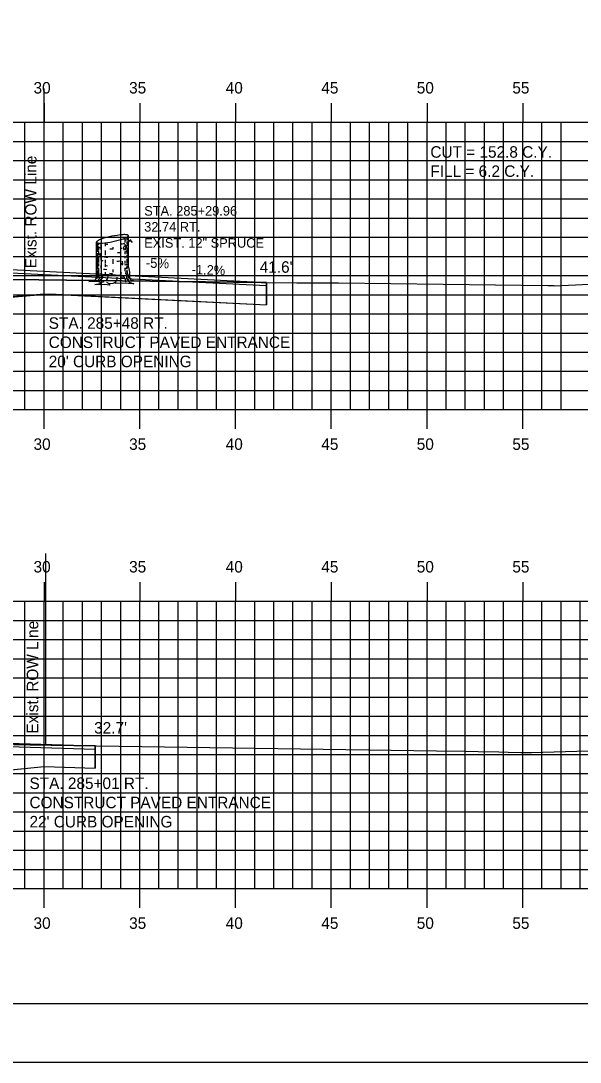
# Model space of a CAD drawing. Extents: x 856680 to 856850, y 366268 to 366378.
# Drawn here: x 856791.9 to 856821.1, y 366268.2 to 366322.5 of the extents above; entities that cross this region are included whole.
import ezdxf

# ---------------------------------------------------------------- set-up
doc = ezdxf.new("R2010")
doc.units = 0
for name, color, linetype in [('ANNOTATION', 7, 'Continuous'), ('BORDER', 7, 'Continuous'), ('D_Roadway_Drive_Gravel_RT', 7, 'Continuous'), ('D_Roadway_Drive_SubGrade', 7, 'Continuous'), ('D_Text_Monospaced', 7, 'Continuous'), ('D_Text_Standard', 7, 'Continuous'), ('E_ROW_Line', 7, 'Continuous'), ('H_V ANNOTATION', 7, 'Continuous'), ('JUNK COM EXC', 7, 'Continuous'), ('MAJOR', 7, 'Continuous'), ('MINOR', 7, 'Continuous'), ('PLOT BOUNDARY', 7, 'Continuous'), ('S_Roadway_Centerline', 7, 'Continuous'), ('S_Trees_Conifer_Pay', 7, 'Continuous')]:
    doc.layers.add(name, color=color, linetype=linetype)

msp = doc.modelspace()

# ---------------------------------------------------------------- linework, layer by layer
at = {"layer": 'BORDER'}
msp.add_line((856688.116, 366271.236), (856848.116, 366271.236), dxfattribs=at)
at = {"layer": 'D_Roadway_Drive_Gravel_RT'}
for p, q in [((856787.117, 366309.756), (856804.736, 366308.875)), ((856787.108, 366309.589), (856804.736, 366308.708)), ((856793.116, 366308.288), (856804.736, 366307.707)), ((856787.112, 366284.786), (856795.791, 366284.523)), ((856787.117, 366284.953), (856795.791, 366284.69)), ((856793.116, 366283.608), (856795.791, 366283.523))]:
    msp.add_line(p, q, dxfattribs=at)
at = {"layer": 'D_Roadway_Drive_SubGrade'}
for p, q in [((856804.736, 366308.875), (856804.736, 366307.708)), ((856783.116, 366307.402), (856793.116, 366308.288)), ((856795.791, 366284.69), (856795.791, 366283.523)), ((856783.116, 366282.599), (856793.116, 366283.608))]:
    msp.add_line(p, q, dxfattribs=at)
at = {"layer": 'E_ROW_Line'}
for p, q in [((856793.119, 366309.007), (856793.119, 366319.007)), ((856793.211, 366284.728), (856793.211, 366294.728))]:
    msp.add_line(p, q, dxfattribs=at)
at = {"layer": 'JUNK COM EXC'}
msp.add_lwpolyline([(856783.116, 366309.234), (856783.116, 366307.402), (856783.116, 366307.402), (856793.404, 366308.273), (856804.736, 366307.707), (856804.736, 366308.874), (856804.736, 366308.874), (856804.446, 366308.878), (856788.463, 366309.06), (856786.682, 366309.152), (856785.792, 366309.195), (856784.53, 366309.232), (856783.77, 366309.239), (856783.307, 366309.238), (856783.116, 366309.234)], dxfattribs=at)
msp.add_lwpolyline([(856783.116, 366284.8), (856783.116, 366282.599), (856783.116, 366282.599), (856793.116, 366283.608), (856795.791, 366283.523), (856795.791, 366284.69), (856793.483, 366284.724), (856792.375, 366284.743), (856791.541, 366284.755), (856789.691, 366284.768), (856786.527, 366284.756), (856783.225, 366284.802)], close=True, dxfattribs=at)
at = {"layer": 'MAJOR'}
for p, q in [((856793.116, 366318.238), (856793.116, 366317.236)), ((856798.116, 366318.238), (856798.116, 366317.236)), ((856803.116, 366318.238), (856803.116, 366317.236)), ((856808.116, 366318.238), (856808.116, 366317.236)), ((856813.116, 366318.238), (856813.116, 366317.236)), ((856818.116, 366318.238), (856818.116, 366317.236)), ((856693.116, 366317.236), (856833.116, 366317.236)), ((856693.116, 366317.236), (856833.116, 366317.236)), ((856793.116, 366302.236), (856793.116, 366317.236)), ((856798.116, 366302.236), (856798.116, 366317.236)), ((856803.116, 366302.236), (856803.116, 366317.236)), ((856808.116, 366302.236), (856808.116, 366317.236)), ((856813.116, 366302.236), (856813.116, 366317.236)), ((856818.116, 366302.236), (856818.116, 366317.236)), ((856693.116, 366312.236), (856833.116, 366312.236)), ((856693.116, 366307.236), (856833.116, 366307.236)), ((856693.116, 366302.236), (856833.116, 366302.236)), ((856693.116, 366302.236), (856833.116, 366302.236)), ((856793.116, 366301.234), (856793.116, 366302.236)), ((856798.116, 366301.234), (856798.116, 366302.236)), ((856803.116, 366301.234), (856803.116, 366302.236)), ((856808.116, 366301.234), (856808.116, 366302.236)), ((856813.116, 366301.234), (856813.116, 366302.236)), ((856818.116, 366301.234), (856818.116, 366302.236)), ((856793.116, 366293.238), (856793.116, 366292.236)), ((856798.116, 366293.238), (856798.116, 366292.236)), ((856803.116, 366293.238), (856803.116, 366292.236)), ((856808.116, 366293.238), (856808.116, 366292.236)), ((856813.116, 366293.238), (856813.116, 366292.236)), ((856818.116, 366293.238), (856818.116, 366292.236)), ((856693.116, 366292.236), (856833.116, 366292.236)), ((856693.116, 366292.236), (856833.116, 366292.236)), ((856793.116, 366277.236), (856793.116, 366292.236)), ((856798.116, 366277.236), (856798.116, 366292.236)), ((856803.116, 366277.236), (856803.116, 366292.236)), ((856808.116, 366277.236), (856808.116, 366292.236)), ((856813.116, 366277.236), (856813.116, 366292.236)), ((856818.116, 366277.236), (856818.116, 366292.236)), ((856693.116, 366287.236), (856833.116, 366287.236)), ((856693.116, 366282.236), (856833.116, 366282.236)), ((856693.116, 366277.236), (856833.116, 366277.236)), ((856693.116, 366277.236), (856833.116, 366277.236)), ((856793.116, 366276.234), (856793.116, 366277.236)), ((856798.116, 366276.234), (856798.116, 366277.236)), ((856803.116, 366276.234), (856803.116, 366277.236)), ((856808.116, 366276.234), (856808.116, 366277.236)), ((856813.116, 366276.234), (856813.116, 366277.236)), ((856818.116, 366276.234), (856818.116, 366277.236))]:
    msp.add_line(p, q, dxfattribs=at)
at = {"layer": 'MINOR'}
for p, q in [((856792.116, 366302.236), (856792.116, 366317.236)), ((856794.116, 366302.236), (856794.116, 366317.236)), ((856795.116, 366302.236), (856795.116, 366317.236)), ((856796.116, 366302.236), (856796.116, 366317.236)), ((856797.116, 366302.236), (856797.116, 366317.236)), ((856799.116, 366302.236), (856799.116, 366317.236)), ((856800.116, 366302.236), (856800.116, 366317.236)), ((856801.116, 366302.236), (856801.116, 366317.236)), ((856802.116, 366302.236), (856802.116, 366317.236)), ((856804.116, 366302.236), (856804.116, 366317.236)), ((856805.116, 366302.236), (856805.116, 366317.236)), ((856806.116, 366302.236), (856806.116, 366317.236)), ((856807.116, 366302.236), (856807.116, 366317.236)), ((856809.116, 366302.236), (856809.116, 366317.236)), ((856810.116, 366302.236), (856810.116, 366317.236)), ((856811.116, 366302.236), (856811.116, 366317.236)), ((856812.116, 366302.236), (856812.116, 366317.236)), ((856814.116, 366302.236), (856814.116, 366317.236)), ((856815.116, 366302.236), (856815.116, 366317.236)), ((856816.116, 366302.236), (856816.116, 366317.236)), ((856817.116, 366302.236), (856817.116, 366317.236)), ((856819.116, 366302.236), (856819.116, 366317.236)), ((856820.116, 366302.236), (856820.116, 366317.236)), ((856693.116, 366316.236), (856833.116, 366316.236)), ((856693.116, 366315.236), (856833.116, 366315.236)), ((856693.116, 366314.236), (856833.116, 366314.236)), ((856693.116, 366313.236), (856833.116, 366313.236)), ((856693.116, 366311.236), (856833.116, 366311.236)), ((856693.116, 366310.236), (856833.116, 366310.236)), ((856693.116, 366309.236), (856833.116, 366309.236)), ((856693.116, 366308.236), (856833.116, 366308.236)), ((856693.116, 366306.236), (856833.116, 366306.236)), ((856693.116, 366305.236), (856833.116, 366305.236)), ((856693.116, 366304.236), (856833.116, 366304.236)), ((856693.116, 366303.236), (856833.116, 366303.236)), ((856792.116, 366277.236), (856792.116, 366292.236)), ((856794.116, 366277.236), (856794.116, 366292.236)), ((856795.116, 366277.236), (856795.116, 366292.236)), ((856796.116, 366277.236), (856796.116, 366292.236)), ((856797.116, 366277.236), (856797.116, 366292.236)), ((856799.116, 366277.236), (856799.116, 366292.236)), ((856800.116, 366277.236), (856800.116, 366292.236)), ((856801.116, 366277.236), (856801.116, 366292.236)), ((856802.116, 366277.236), (856802.116, 366292.236)), ((856804.116, 366277.236), (856804.116, 366292.236)), ((856805.116, 366277.236), (856805.116, 366292.236)), ((856806.116, 366277.236), (856806.116, 366292.236)), ((856807.116, 366277.236), (856807.116, 366292.236)), ((856809.116, 366277.236), (856809.116, 366292.236)), ((856810.116, 366277.236), (856810.116, 366292.236)), ((856811.116, 366277.236), (856811.116, 366292.236)), ((856812.116, 366277.236), (856812.116, 366292.236)), ((856814.116, 366277.236), (856814.116, 366292.236)), ((856815.116, 366277.236), (856815.116, 366292.236)), ((856816.116, 366277.236), (856816.116, 366292.236)), ((856817.116, 366277.236), (856817.116, 366292.236)), ((856819.116, 366277.236), (856819.116, 366292.236)), ((856820.116, 366277.236), (856820.116, 366292.236)), ((856821.116, 366277.236), (856821.116, 366292.236)), ((856693.116, 366291.236), (856833.116, 366291.236)), ((856693.116, 366290.236), (856833.116, 366290.236)), ((856693.116, 366289.236), (856833.116, 366289.236)), ((856693.116, 366288.236), (856833.116, 366288.236)), ((856693.116, 366286.236), (856833.116, 366286.236)), ((856693.116, 366285.236), (856833.116, 366285.236)), ((856693.116, 366284.236), (856833.116, 366284.236)), ((856693.116, 366283.236), (856833.116, 366283.236)), ((856693.116, 366281.236), (856833.116, 366281.236)), ((856693.116, 366280.236), (856833.116, 366280.236)), ((856693.116, 366279.236), (856833.116, 366279.236)), ((856693.116, 366278.236), (856833.116, 366278.236))]:
    msp.add_line(p, q, dxfattribs=at)
at = {"layer": 'PLOT BOUNDARY'}
msp.add_lwpolyline([(856680.023, 366268.177), (856850.023, 366268.177), (856850.023, 366378.177), (856680.023, 366378.177)], close=True, dxfattribs=at)
at = {"layer": 'S_Roadway_Centerline'}
for points in [[(856788.463, 366309.06), (856804.446, 366308.878), (856806.319, 366308.852), (856807.253, 366308.849), (856807.696, 366308.849), (856808.101, 366308.85), (856808.281, 366308.851), (856808.489, 366308.853), (856819.433, 366308.709), (856819.506, 366308.709), (856819.606, 366308.709), (856819.725, 366308.708), (856819.769, 366308.707), (856821.607, 366308.779), (856833.116, 366308.838)], [(856791.541, 366284.755), (856792.375, 366284.743), (856793.483, 366284.724), (856813.618, 366284.43), (856815.099, 366284.402), (856815.786, 366284.389), (856816.868, 366284.367), (856817.354, 366284.358), (856818.009, 366284.346), (856818.571, 366284.337), (856826.84, 366284.577), (856827.6, 366284.998)]]:
    msp.add_lwpolyline(points, dxfattribs=at)
at = {"layer": 'S_Trees_Conifer_Pay'}
for p, q in [((856797.517, 366309.668), (856797.517, 366311.315)), ((856795.853, 366309.258), (856795.853, 366310.98)), ((856795.9, 366310.942), (856795.9, 366310.471)), ((856795.959, 366310.931), (856795.959, 366310.833)), ((856795.959, 366310.759), (856795.959, 366310.555)), ((856796.084, 366310.923), (856796.084, 366310.691)), ((856796.304, 366310.943), (856796.304, 366310.775)), ((856797.1, 366310.985), (856797.1, 366310.786)), ((856797.1, 366310.728), (856797.1, 366310.64)), ((856797.328, 366311.182), (856797.328, 366310.959)), ((856797.328, 366310.87), (856797.328, 366310.823)), ((856797.446, 366311.243), (856797.446, 366311.08)), ((856797.446, 366311.012), (856797.446, 366310.884)), ((856795.9, 366310.407), (856795.9, 366310.098)), ((856795.959, 366310.497), (856795.959, 366310.298)), ((856795.959, 366310.251), (856795.959, 366309.915)), ((856796.084, 366310.65), (856796.084, 366310.576)), ((856796.084, 366310.172), (856796.084, 366310.034)), ((856796.304, 366310.539), (856796.304, 366310.302)), ((856796.709, 366310.712), (856796.709, 366310.617)), ((856797.1, 366310.292), (856797.1, 366310.187)), ((856797.328, 366310.487), (856797.328, 366310.356)), ((856797.328, 366310.245), (856797.328, 366310.135)), ((856797.385, 366310.687), (856797.334, 366310.627)), ((856797.446, 366310.697), (856797.446, 366310.361)), ((856797.446, 366310.325), (856797.446, 366310.162)), ((856795.9, 366310.051), (856795.9, 366309.559)), ((856795.959, 366309.861), (856795.959, 366309.726)), ((856796.084, 366309.762), (856796.084, 366309.621)), ((856796.304, 366310.057), (856796.304, 366309.905)), ((856796.304, 366309.861), (856796.304, 366309.688)), ((856796.709, 366310.098), (856796.709, 366310.024)), ((856796.709, 366309.999), (856796.709, 366309.851)), ((856797.1, 366309.82), (856797.1, 366309.674)), ((856797.328, 366309.999), (856797.328, 366309.857)), ((856797.328, 366309.63), (856797.328, 366309.458)), ((856797.446, 366310.115), (856797.446, 366309.898)), ((856797.446, 366309.867), (856797.446, 366309.793)), ((856797.446, 366309.753), (856797.446, 366309.579)), ((856795.9, 366309.505), (856795.9, 366309.258)), ((856795.959, 366309.627), (856795.959, 366309.248)), ((856796.084, 366309.359), (856796.084, 366309.264)), ((856796.304, 366309.411), (856796.304, 366309.258)), ((856796.709, 366309.559), (856796.709, 366309.406)), ((856797.1, 366309.441), (856797.1, 366309.353)), ((856796.084, 366308.865), (856796.247, 366308.928)), ((856796.521, 366308.8), (856796.395, 366308.865))]:
    msp.add_line(p, q, dxfattribs=at)
for points in [[(856797.301, 366310.775), (856797.27, 366310.691), (856797.266, 366310.623), (856797.297, 366310.56)], [(856797.334, 366310.813), (856797.371, 366310.739), (856797.418, 366310.796), (856797.476, 366310.864), (856797.568, 366311.058), (856797.633, 366311.105), (856797.663, 366311.111)], [(856797.348, 366310.56), (856797.385, 366310.687), (856797.449, 366310.802), (856797.48, 366310.87), (856797.549, 366311.016)], [(856797.563, 366311.046), (856797.639, 366311.054), (856797.711, 366310.955)], [(856796.032, 366310.285), (856796.026, 366310.38), (856796.07, 366310.357), (856796.07, 366310.263)], [(856797.517, 366309.668), (856797.568, 366309.406), (856797.585, 366309.132), (856797.642, 366309.007), (856797.778, 366308.976), (856797.548, 366308.939), (856797.548, 366308.939), (856797.554, 366308.892), (856797.801, 366308.797), (856797.527, 366308.814), (856797.171, 366308.834), (856796.85, 366308.823), (856796.856, 366308.906), (856796.708, 366308.823), (856796.521, 366308.8), (856796.545, 366308.733), (856796.278, 366308.776), (856796.057, 366308.749), (856795.764, 366308.766), (856796.053, 366308.823), (856796.084, 366308.865), (856795.921, 366308.922), (856795.684, 366308.933), (856795.444, 366308.933), (856795.785, 366308.991), (856795.827, 366309.071), (856795.853, 366309.258)], [(856797.171, 366309.886), (856797.184, 366309.81), (856797.231, 366309.82), (856797.219, 366309.987)], [(856795.901, 366309.211), (856795.88, 366309.132), (856795.86, 366309.038)], [(856795.979, 366309.19), (856795.985, 366309.075), (856795.932, 366308.986), (856795.921, 366308.922)], [(856796.142, 366309.217), (856796.142, 366309.085), (856796.053, 366308.986)], [(856796.368, 366308.976), (856796.436, 366309.071), (856796.463, 366309.211)], [(856796.856, 366308.906), (856796.931, 366309.048), (856796.94, 366309.149)], [(856797.107, 366309.275), (856797.118, 366309.149), (856797.192, 366309.106)], [(856797.385, 366308.886), (856797.371, 366309.024), (856797.297, 366309.153)], [(856797.344, 366309.38), (856797.418, 366309.275), (856797.423, 366309.102), (856797.548, 366308.939)], [(856797.443, 366309.525), (856797.449, 366309.38), (856797.496, 366309.312), (856797.507, 366309.112)]]:
    msp.add_lwpolyline(points, dxfattribs=at)
for centre, radius, start, end in [((856797.709, 366306.212), 5.179, 101.7194, 108.0594), ((856797.709, 366306.212), 5.179, 95.3794, 101.7194), ((856797.299, 366310.57), 0.802, 79.2194, 95.3794), ((856797.018, 366311.921), 0.802, 288.0594, 304.2194), ((856797.402, 366311.111), 0.251, 71.0501, 79.2194), ((856797.328, 366311.465), 0.251, 304.2194, 312.3887), ((856797.456, 366311.271), 0.0817, 56.7194, 71.0501), ((856797.442, 366311.34), 0.0817, 312.3887, 326.7194), ((856797.472, 366311.295), 0.0527, 46.923, 56.7194), ((856797.487, 366311.311), 0.0314, 34.2194, 46.923), ((856797.466, 366311.324), 0.0527, 326.7194, 336.5158), ((856797.491, 366311.314), 0.0264, 23.4074, 34.2194), ((856797.495, 366311.315), 0.0226, 11.7194, 23.4074), ((856797.486, 366311.316), 0.0314, 336.5158, 349.2194), ((856797.495, 366311.315), 0.0226, 0.0315, 11.7194), ((856797.491, 366311.315), 0.0264, 349.2194, 0.0315), ((856795.885, 366310.801), 0.0334, 163.9485, 180), ((856795.885, 366310.801), 0.0334, 180, 196.0515), ((856795.88, 366310.979), 0.0264, 169.2194, 180.0315), ((856795.876, 366310.979), 0.0226, 180.0315, 191.7194), ((856795.896, 366310.804), 0.0441, 196.0515, 210), ((856795.885, 366310.978), 0.0314, 156.5158, 169.2194), ((856795.876, 366310.979), 0.0226, 191.7194, 203.4074), ((856795.879, 366310.981), 0.0264, 203.4074, 214.2194), ((856795.904, 366310.97), 0.0527, 146.7194, 156.5158), ((856795.883, 366310.984), 0.0314, 214.2194, 226.923), ((856795.911, 366310.813), 0.0624, 210, 228.7494), ((856795.928, 366310.954), 0.0817, 132.3887, 146.7194), ((856795.898, 366310.999), 0.0527, 226.923, 236.7194), ((856795.914, 366311.023), 0.0817, 236.7194, 251.0501), ((856795.984, 366310.896), 0.172, 228.7494, 240), ((856796.042, 366310.829), 0.251, 124.2194, 132.3887), ((856795.969, 366311.183), 0.251, 251.0501, 259.2194), ((856796.183, 366311.241), 0.571, 240, 240.3367), ((856796.352, 366310.374), 0.802, 108.0594, 124.2194), ((856796.072, 366311.724), 0.802, 259.2194, 275.3794), ((856796.183, 366311.241), 0.571, 246.8597, 257.9846), ((856795.661, 366316.082), 5.179, 275.3794, 281.7194), ((856796.685, 366314.991), 4.124, 264.6955, 266.7331), ((856795.661, 366316.082), 5.179, 281.7194, 288.0594), ((856796.685, 366314.991), 4.124, 276.238, 278.1032), ((856797.186, 366311.474), 0.571, 278.1032, 284.3667), ((856797.186, 366311.628), 0.571, 284.4317, 292.4132), ((856797.186, 366311.474), 0.571, 297.0237, 300), ((856797.385, 366311.283), 0.172, 300, 311.2506), ((856797.385, 366311.129), 0.172, 300, 311.2506), ((856797.458, 366311.201), 0.0624, 311.2506, 330), ((856797.458, 366311.046), 0.0624, 311.2506, 330), ((856797.474, 366311.192), 0.0441, 330, 343.9485), ((856797.474, 366311.037), 0.0441, 330, 343.9485), ((856797.484, 366311.189), 0.0334, 343.9485, 354.2151), ((856797.484, 366311.034), 0.0334, 343.9485, 354.2151), ((856795.885, 366310.354), 0.0334, 163.9485, 180), ((856795.885, 366310.354), 0.0334, 180, 196.0515), ((856795.896, 366310.357), 0.0441, 196.0515, 210), ((856795.911, 366310.367), 0.0624, 210, 228.7494), ((856795.984, 366310.449), 0.172, 228.7494, 240), ((856796.183, 366310.794), 0.571, 240, 240.3367), ((856796.184, 366311.03), 0.571, 240, 247.0587), ((856796.684, 366314.312), 4.124, 264.081, 266.6676), ((856796.684, 366314.759), 4.124, 268.0751, 270), ((856796.684, 366314.759), 4.124, 270, 270.3581), ((856796.685, 366314.548), 4.124, 273.7052, 275.9504), ((856796.684, 366314.759), 4.124, 275.7849, 277.0558), ((856796.684, 366314.312), 4.124, 277.6125, 278.1032), ((856797.185, 366310.794), 0.571, 278.1032, 286.9296), ((856797.186, 366311.03), 0.571, 284.4493, 297.0429), ((856797.185, 366310.794), 0.571, 297.1896, 300), ((856797.384, 366310.449), 0.172, 300, 311.2506), ((856797.456, 366310.367), 0.0624, 311.2506, 330), ((856797.472, 366310.357), 0.0441, 330, 343.9485), ((856797.483, 366310.354), 0.0334, 343.9485, 354.2151), ((856797.484, 366310.59), 0.0334, 343.9485, 354.2151), ((856795.885, 366310.144), 0.0334, 163.9485, 180), ((856795.885, 366310.144), 0.0334, 180, 196.0515), ((856795.885, 366309.908), 0.0334, 163.9485, 180), ((856795.885, 366309.908), 0.0334, 180, 196.0515), ((856795.885, 366309.71), 0.0334, 163.9485, 180), ((856795.896, 366310.147), 0.0441, 196.0515, 210), ((856795.896, 366309.911), 0.0441, 196.0515, 210), ((856795.911, 366310.157), 0.0624, 210, 228.7494), ((856795.911, 366309.92), 0.0624, 210, 228.7494), ((856795.984, 366310.239), 0.172, 228.7494, 240), ((856795.984, 366310.002), 0.172, 228.7494, 240), ((856796.183, 366310.584), 0.571, 240, 246.8597), ((856796.183, 366310.347), 0.571, 240, 246.8597), ((856796.172, 366310.156), 0.571, 241.2369, 248.0268), ((856796.183, 366310.584), 0.571, 259.2707, 261.8968), ((856796.684, 366314.102), 4.124, 261.8968, 263.1474), ((856796.684, 366313.865), 4.124, 264.716, 266.3193), ((856796.684, 366314.102), 4.124, 270, 270.3581), ((856796.684, 366314.102), 4.124, 273.1493, 275.4569), ((856797.185, 366310.347), 0.571, 285.3983, 297.1896), ((856797.185, 366310.15), 0.571, 289.2907, 300), ((856797.185, 366310.584), 0.571, 297.1896, 300), ((856797.384, 366310.239), 0.172, 300, 311.2506), ((856797.384, 366309.805), 0.172, 300, 311.2506), ((856797.456, 366310.157), 0.0624, 311.2506, 330), ((856797.456, 366309.722), 0.0624, 311.2506, 330), ((856797.472, 366310.147), 0.0441, 330, 343.9485), ((856797.472, 366309.713), 0.0441, 330, 343.9485), ((856797.483, 366310.144), 0.0334, 343.9485, 354.2151), ((856797.483, 366309.71), 0.0334, 343.9485, 354.2151), ((856795.885, 366309.514), 0.0334, 163.9485, 180), ((856795.885, 366309.514), 0.0334, 180, 196.0515), ((856795.885, 366309.294), 0.0334, 163.9485, 180), ((856795.885, 366309.294), 0.0334, 180, 196.0515), ((856795.896, 366309.517), 0.0441, 196.0515, 210), ((856795.896, 366309.297), 0.0441, 196.0515, 210), ((856795.911, 366309.527), 0.0624, 210, 228.7494), ((856795.911, 366309.306), 0.0624, 210, 228.7494), ((856795.984, 366309.609), 0.172, 228.7494, 240), ((856795.984, 366309.389), 0.172, 228.7494, 240), ((856796.183, 366309.954), 0.571, 240, 246.8597), ((856796.183, 366309.734), 0.571, 240, 244.5314), ((856796.684, 366313.251), 4.124, 262.4438, 263.512), ((856796.684, 366313.667), 4.124, 263.4991, 265.8397), ((856796.684, 366313.472), 4.124, 267.8117, 270), ((856796.684, 366313.472), 4.124, 270, 270.1328), ((856796.684, 366313.472), 4.124, 275.7849, 276.7896), ((856796.684, 366313.251), 4.124, 277.3684, 278.1032), ((856797.185, 366309.734), 0.571, 278.1032, 281.637), ((856797.185, 366309.954), 0.571, 288.5067, 297.2721), ((856797.384, 366309.389), 0.172, 300, 311.2506), ((856797.456, 366309.306), 0.0624, 311.2506, 330), ((856797.472, 366309.297), 0.0441, 330, 343.9485), ((856797.483, 366309.294), 0.0334, 343.9485, 354.2151)]:
    msp.add_arc(centre, radius, start, end, dxfattribs=at)

# ---------------------------------------------------------------- texts
at = {"layer": 'ANNOTATION'}
for s, p in [('CUT = 152.8 C.Y.', (856813.292, 366315.386)), ('FILL = 6.2 C.Y.', (856813.292, 366314.384)), ('STA. 285+48 RT.', (856793.357, 366306.455)), ('CONSTRUCT PAVED ENTRANCE', (856793.357, 366305.453)), ("20' CURB OPENING", (856793.357, 366304.451)), ('STA. 285+01 RT.', (856792.353, 366282.434)), ('CONSTRUCT PAVED ENTRANCE', (856792.353, 366281.432)), ("22' CURB OPENING", (856792.353, 366280.43))]:
    msp.add_text(s, height=0.6, dxfattribs=at).set_placement(p)
msp.add_text('-5%', height=0.51, rotation=357.7094, dxfattribs=at).set_placement((856798.422, 366309.653))
at = {"layer": 'D_Text_Monospaced'}
for s, height, p in [('STA. 285+29.96', 0.49998, (856798.345, 366312.362)), ('32.74 RT.', 0.5, (856798.345, 366311.528)), ('EXIST. 12" SPRUCE', 0.49998, (856798.345, 366310.688))]:
    msp.add_text(s, height=height, dxfattribs=at).set_placement(p)
msp.add_text('-1.2%', height=0.5, rotation=358.3318, dxfattribs=at).set_placement((856800.82, 366309.306))
at = {"layer": 'D_Text_Standard'}
for s, p in [("41.6'", (856804.378, 366309.381)), ("32.7'", (856795.73, 366285.329))]:
    msp.add_text(s, height=0.6, dxfattribs=at).set_placement(p)
at = {"layer": 'E_ROW_Line'}
for p in [(856792.719, 366309.607), (856792.811, 366285.328)]:
    msp.add_text('Exist. ROW Line', height=0.6, rotation=90, dxfattribs=at).set_placement(p)
at = {"layer": 'H_V ANNOTATION'}
for s, p in [('30', (856792.565, 366318.736)), ('35', (856797.557, 366318.736)), ('40', (856802.602, 366318.736)), ('45', (856807.594, 366318.736)), ('50', (856812.581, 366318.736)), ('55', (856817.573, 366318.736)), ('30', (856792.565, 366300.136)), ('35', (856797.557, 366300.136)), ('40', (856802.602, 366300.136)), ('45', (856807.594, 366300.136)), ('50', (856812.581, 366300.136)), ('55', (856817.573, 366300.136)), ('30', (856792.565, 366293.736)), ('35', (856797.557, 366293.736)), ('40', (856802.602, 366293.736)), ('45', (856807.594, 366293.736)), ('50', (856812.581, 366293.736)), ('55', (856817.573, 366293.736)), ('30', (856792.565, 366275.136)), ('35', (856797.557, 366275.136)), ('40', (856802.602, 366275.136)), ('45', (856807.594, 366275.136)), ('50', (856812.581, 366275.136)), ('55', (856817.573, 366275.136))]:
    msp.add_text(s, height=0.6, dxfattribs=at).set_placement(p)

doc.saveas('drawing.dxf')
